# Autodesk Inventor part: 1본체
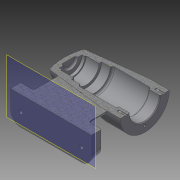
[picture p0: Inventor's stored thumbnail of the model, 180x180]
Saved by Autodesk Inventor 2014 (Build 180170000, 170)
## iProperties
Created: 2017-01
Part Number: 1본체
Material: 일반
Document SubType Name: Modeling
Designer: owner
Density: 1 g/cm^3
Appearance: 기본값
Author: owner
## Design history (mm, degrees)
sketch "스케치1"
  geometry: L1 (0, 0)-(112, 0); L2 (6, 0)-(6, 10.5); L3 (6, 10.5)-(9, 10.5); L4 (9, 10.5)-(9, 16); L5 (9, 16)-(13, 16); L6 (13, 16)-(13, 17.5); L7 (13, 17.5)-(31, 17.5); L8 (31, 17.5)-(31, 21); L9 (97, 24)-(97, 21); L10 (112, 12.806)-(112, 0); L11 (97, 21)-(112, 21); L12 (3.73, 24.144)-(84, 34); L13 (84, 34)-(112, 34); L14 (31, 21)-(43, 21); L15 (43, 21)-(43, 24); L16 (43, 24)-(97, 24); L17 (112, 34)-(112, 21); A1 r 80 centre (80, 0) between (3.73, 24.144) and (0, 0); 1 further point
  constraints: 34 end point, 8 perpendicular, 5 parallel, 2 point on circle, 2 point on line, 1 centre point, 1 coincident, 1 horizontal, 1 vertical alignment
  dimensions: "d0" = 112 distance of L1.start L1.end; "d12" = 7 deg angle of L12 L13; "d13" = 28 distance of L12.end L13.end; "d18" = 68 diameter of L13.end L1; "d22" = 42 diameter of L11 L1; "d23" = 15 distance of L9.end L11.end; "d24" = 54 distance of L15.end L9.start; "d25" = 12 distance of L8.end L14.end; "d26" = 3 distance of L2.end L3.end; "d27" = 4 distance of L4.end L5.end; "d28" = 18 distance of L6.end L7.end; "d29" = 48 diameter of L16 L1; "d30" = 42 diameter of L14 L1; "d31" = 35 diameter of L7 L1; "d32" = 32 diameter of L5 L1; "d33" = 21 diameter of L3 L1; "d34" = 80 radius of A1
revolve "회전1" sketch "스케치1" stored, may be unused: angle "d35" = 90 deg
node "작업 평면1"
sketch "스케치2"
  geometry: L1 (-112, 34)-(0, 34); L2 (0, 34)-(0, -36); L3 (0, -36)-(-112, -36); L4 (-112, -36)-(-112, 34); L5 (-84, 34)-(-112, 34) reference; L6 (-112, 34)-(-112, -34) reference; 1 further point
  constraints: 8 end point, 2 coincident, 2 parallel, 1 horizontal, 1 perpendicular
  dimensions: "d37" = 112 distance of L1.start L1.end; "d38" = 70 distance of L1.end L2.end
extrude "돌출1" join sketch "스케치2" distance "d39" = 14; taper "d40" = 0 deg
feature "면 기울기1" dims angle "d55" = -15 deg
sketch "스케치6"
  geometry: L1 (112, -60)-(0, -60) reference; L2 (3.73, -24.144)-(84, -34) reference; L3 (84, -34)-(112, -34) reference; L4 (94, -60)-(94, -34); L5 (56, -30.562)-(56, -60); L6 (0, -60)-(112, -60) reference; 3 further points
  constraints: 4 end point, 3 midpoint, 3 point on line, 2 perpendicular, 1 vertical alignment
  dimensions: "d58" = 18 distance from line of L4 L1.start
extrude "돌출3" join sketch "스케치6" stored distance "d60" = 8; taper "d61" = 0 deg
node "작업 평면2"
sketch "스케치8"
  geometry: L1 (-30.562, 0)-(-34, 0) reference; L2 (-60, -36)-(-60, 30.249) reference; L3 (-24.843, -17.801)-(-60, -24); L4 (-30.562, 0)-(-60, 0); C1 r 24.144 at (0, 0) reference; A1 r 30.562 centre (0, 0) between (-30.562, 0) and (-24.843, -17.801); 2 further points
  constraints: 4 end point, 2 point on circle, 2 point on line, 1 centre point, 1 coincident, 1 horizontal alignment, 1 perpendicular
  dimensions: "d66" = 12 distance of L3.end L2.start; "d67" = 100 deg angle of L3 L2
extrude "돌출5" join sketch "스케치8" stored distance "d69" = 8; taper "d70" = 0 deg
sketch "스케치10"
  geometry: L1 (3.73, -24.144)-(84, -34) reference; L2 (112, -60)-(0, -60) reference; L3 (18, -25.896)-(18, -60); L4 (0, -74)-(0, -60) reference; L5 (52, -24.843)-(52, -60) reference; L6 (18, -60)-(52, -60); L7 (52, -30.071)-(18, -25.896); 1 further point
  constraints: 6 end point, 4 point on line, 2 collinear, 1 perpendicular
  dimensions: "d71" = 18 distance between parallel lines of L3 L4
extrude "돌출6" join sketch "스케치10" stored distance "d72" = 8; taper "d73" = 0 deg
fillet "모깎기2" dims "d74" = 14
fillet "모깎기3" dims "d75" = 14
sketch "스케치11" dims "d76" = 10
  geometry: L1 (16.887, 26.506)-(19.774, 21.506); L2 (19.774, 21.506)-(16.887, 16.506); L3 (16.887, 16.506)-(11.113, 16.506); L4 (11.113, 16.506)-(8.226, 21.506); L5 (8.226, 21.506)-(11.113, 26.506); L6 (11.113, 26.506)-(16.887, 26.506); 7 further points; 1 other entity
  constraints: 12 end point, 2 coincident, 1 midpoint, 1 vertical alignment, 16 other
  dimensions: "d106" = 5 vertical distance of L1.start L1.end
fillet "모깎기4" dims "d79" = 1
sketch "스케치12"
  geometry: C1 r 34 at (0, 0) reference; 1 further point
  constraints: 1 vertical alignment
  dimensions: "d95" = 26 distance of point (0, 26) C1.centre
hole "구멍2" sketch "스케치12" at (0, 26) diameter "d96" = 3.242; stored, may be unused: countersink angle "d100" = 90 deg, drill point angle "d102" = 118 deg; dims "d97" = 8, "d98" = 4, "d99" = 2, "d101" = 11
extrude "돌출8" cut sketch "스케치11" distance "d107" = 4; taper "d108" = 0 deg
sketch "스케치14"
  geometry: L1 (11.113, 26.506)-(16.887, 26.506) reference; C1 r 2.5 at (14, 21.506); 3 further points
  constraints: 1 centre point, 1 horizontal alignment, 1 midpoint, 1 vertical alignment
  dimensions: "d112" = 5 diameter of C1
extrude "돌출10" cut sketch "스케치14" stored distance "d113" = 4; taper "d114" = 0 deg
fillet "모깎기5" dims "d121" = 0.3
chamfer "모따기1" distance "d123" = 1; stored, may be unused: second distance "d124" = 2, angle "d125" = 45 deg
fillet "모깎기7" dims "d126" = 3
fillet "모깎기8" dims "d127" = 3
fillet "모깎기9" dims "d128" = 3
fillet "모깎기10" dims "d129" = 3
fillet "모깎기11" dims "d130" = 3
fillet "모깎기12" dims "d131" = 3
fillet "모깎기13" dims "d135" = 2
fillet "모깎기14" dims "d136" = 2
sketch "스케치15"
  geometry: L1 (84, 0)-(0, 0) reference; L2 (98, 3.751)-(98, 17.21) reference; 2 further points
  constraints: 1 other
  dimensions: "d137" = 56 distance from line of point (42, 4) L2; "d138" = 4 distance from line of point (42, 4) L1
feature "엠보싱1" sketch "스케치15" dims "d0" = 112, "d139" = 0.5, "d140" = 0
fillet "모깎기15" dims "d141" = 3
fillet "모깎기16" dims "d142" = 3
node "솔리드1"
mirror "대칭1"
pattern_linear "직사각형 패턴2" dims "d117" = 42, "d120" = 84
pattern_circular "원형 패턴2" dims angle "d133" = 360 deg
node "투영된 루프2"
node "작업 평면3"
other parameters: "d36" = -74
